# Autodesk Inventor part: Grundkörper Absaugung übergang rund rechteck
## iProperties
Author: WN
Shininess: 20.0
Angle Display Precision: 2
Document Length Units: 11269
Document Angle Units: 11283
Document Time Units: 11279
Document Mass Units: 11290
Document Length Units Precision: 3
Document Angle Units Precision: 2
Compacted: False
PropertySet Name: _Private Model Information
Created: 2003-03
Part Number: Grundkörper Absaugung übergang rund rechteck
Material: Standard
Document SubType Name: Modellieren
Designer: WN
Control State: 0
Master: False
Checked Out: False
PropertySet Name: Design Tracking Control
Density: 0.0
Volumn: 0.0
Area: 0.0
PropertySet Name: Model Information
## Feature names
1. Erhebung1
2. Extrusion1
3. Extrusion2
4. Extrusion3
5. Extrusion4
6. Extrusion5
7. Extrusion6
8. Extrusion7
9. Extrusion8
10. Extrusion9
11. Extrusion10
12. Extrusion11
13. Extrusion12
14. Extrusion13
15. Extrusion14
16. Extrusion15
17. Extrusion16
18. Extrusion17
